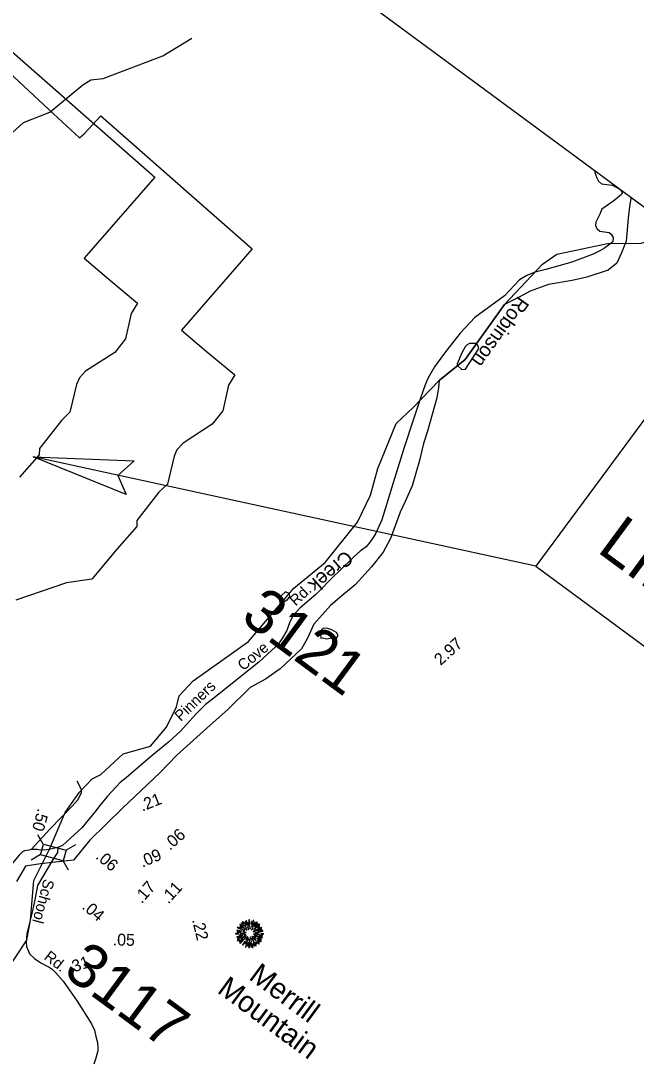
# Model space of a CAD drawing. Extents: x 945666 to 965748, y 644452 to 663300.
# Drawn here: x 954740 to 955579, y 658587 to 660009 of the extents above; entities that cross this region are included whole.
import ezdxf

# ---------------------------------------------------------------- set-up
doc = ezdxf.new("R2010")
doc.units = 0
for name, color, linetype in [('Exist Boundary Political City Limit New', 7, 'Continuous'), ('Exist Boundary Political Urban Extension UEB', 7, 'Continuous'), ('Exist Geographical Mountain Summit CELL', 7, 'Continuous'), ('Exist Geographical Mountain Summit Label', 7, 'Continuous'), ('Exist Hydrographic Creek Single Shore', 7, 'Continuous'), ('Exist Hydrographic Pond Under 1500 Sq Ft', 7, 'Continuous'), ('Exist Road Secondary Mileage Tenths English Label', 7, 'Continuous'), ('Exist Road Secondary Structure Standard Bridge CELL', 7, 'Continuous'), ('Exist Road Secondary Type 51 Attributed', 7, 'Continuous'), ('Exist Road Secondary Type 51 Label', 7, 'Continuous'), ('Old_Level_1', 7, 'Continuous'), ('Old_Level_28', 7, 'Continuous'), ('Old_Level_48', 7, 'Continuous'), ('Prop EOT', 7, 'Continuous'), ('Prop Paved Shoulder', 7, 'Continuous'), ('Prop Terminator CELL', 7, 'Continuous')]:
    doc.layers.add(name, color=color, linetype=linetype)

msp = doc.modelspace()

# ---------------------------------------------------------------- linework, layer by layer
at = {"layer": 'Exist Boundary Political City Limit New'}
msp.add_lwpolyline([(954716, 659977.3), (954922.3, 659795.6), (954826, 659685), (954859.6, 659656.3), (954898.7, 659623.7), (954890, 659609.6), (954882.3, 659575), (954867.7, 659556.4), (954828.1, 659530.8), (954819.8, 659521.7), (954815.8, 659512.9), (954806.6, 659474.9), (954795.1, 659463.6), (954765.2, 659425.2), (954764.8, 659416.9), (954738.1, 659386.3)], dxfattribs=at)
at = {"layer": 'Exist Boundary Political Urban Extension UEB'}
msp.add_lwpolyline([(955572.1, 659768.2), (955570.4, 659758.8), (955568.2, 659739.6), (955565.2, 659708.1), (955558.8, 659692.3), (955552.7, 659678.3), (955540.7, 659668.8), (955511.9, 659659.3), (955491.9, 659654.7), (955459.3, 659649.2), (955434.3, 659640.2), (955418.4, 659631.4), (955413, 659628.8), (955399.4, 659621.7), (955345.6, 659546.9), (955310.4, 659518.1), (955309.2, 659508.6), (955307.2, 659494.5), (955294.5, 659448.8), (955289, 659432.3), (955283.7, 659409.1), (955273.6, 659374.3), (955263.7, 659352.8), (955257.3, 659338.5), (955243.8, 659302.4), (955234.1, 659283.7), (955217.9, 659263.7), (955195.8, 659239.4), (955177.6, 659224.5), (955161.9, 659211), (955139.4, 659185.5), (955130.6, 659166.7), (955122.3, 659151.8), (955093.4, 659124.5), (955073.6, 659110.8), (955052.5, 659099.1), (955022.4, 659069.7), (954993.3, 659043.5), (954952.4, 659006.7), (954929.2, 658982.9), (954878.3, 658934.6), (954834, 658891), (954811.5, 658863.6), (954766.3, 658858.6), (954745.9, 658855.4), (954733.6, 658834.7)], dxfattribs=at)
at = {"layer": 'Exist Geographical Mountain Summit CELL'}
for points in [[(955035.3, 658772), (955035.1, 658771.3), (955039.7, 658769.6), (955039.7, 658770.1)], [(955038.3, 658773), (955041.5, 658770.9), (955041.8, 658771.3), (955038.6, 658773.7)], [(955038.4, 658775.8), (955045.4, 658769.5), (955045.7, 658769.8), (955038.8, 658776.3)], [(955040.3, 658777.8), (955043.9, 658773.6), (955044.3, 658773.9), (955040.8, 658778.2)], [(955042.1, 658779.6), (955043.8, 658776.9), (955044.1, 658777.2), (955042.6, 658780)], [(955044.8, 658774.8), (955047.1, 658771.2), (955047.4, 658771.4), (955045.3, 658775.1)], [(955045.2, 658779), (955046.6, 658775.3), (955047.1, 658775.4), (955045.8, 658779.2)], [(955046.8, 658780.9), (955048.6, 658774.7), (955049, 658774.8), (955047.5, 658781.1)], [(955049, 658772.6), (955050.2, 658768.7), (955050.6, 658768.8), (955049.5, 658772.7)], [(955049.5, 658778.4), (955050.7, 658772.9), (955051.1, 658772.9), (955050.2, 658778.8)], [(955050.8, 658782), (955051.7, 658775.3), (955052.2, 658775.3), (955051.6, 658782.1)], [(955052.1, 658772.5), (955052.3, 658769.7), (955052.7, 658769.7), (955052.7, 658772.5)], [(955053.8, 658780), (955053.8, 658776.5), (955054.1, 658776.5), (955054.5, 658780.1)], [(955056.6, 658781.4), (955054.2, 658772.4), (955054.6, 658772.3), (955057.4, 658781.3)], [(955056.2, 658773.4), (955056.5, 658773.3), (955059.2, 658779), (955058.7, 658779.2)], [(955056.6, 658766.1), (955056.8, 658765.7), (955068.4, 658770.8), (955068.1, 658771.6)], [(955058, 658768.6), (955065.5, 658775.6), (955065, 658776.2), (955057.7, 658769)], [(955061.4, 658779.4), (955057.8, 658773.7), (955058.2, 658773.5), (955062.1, 658779.1)], [(955058.9, 658772.5), (955059.3, 658772.2), (955063.3, 658776.9), (955062.8, 658777.3)], [(955062.5, 658771), (955062.8, 658770.6), (955065.9, 658772.7), (955065.5, 658773.2)], [(955032.6, 658763.6), (955032.6, 658763), (955037.2, 658763), (955037.2, 658763.5)], [(955034.2, 658768.3), (955034.2, 658767.6), (955040.4, 658766.2), (955040.6, 658766.8)], [(955034.3, 658759.2), (955034.4, 658758.7), (955042.3, 658760.5), (955042.2, 658761)], [(955034.8, 658765.3), (955039.2, 658764.8), (955039.2, 658765.3), (955035, 658766)], [(955040.9, 658759.4), (955035.3, 658757.2), (955035.4, 658756.7), (955041.1, 658758.8)], [(955038.3, 658761.3), (955041.7, 658761.7), (955041.6, 658762.2), (955038.1, 658761.9)], [(955038.3, 658750.5), (955038.7, 658750), (955046.9, 658758.3), (955046.7, 658758.7)], [(955039.4, 658763.5), (955039.4, 658762.9), (955045.2, 658763.2), (955045.2, 658763.6)], [(955039.6, 658756.9), (955039.9, 658756.3), (955047.2, 658760.4), (955047, 658760.7)], [(955041, 658769.6), (955040.8, 658769), (955044.9, 658767.3), (955045.1, 658767.8)], [(955042.8, 658766), (955042.7, 658765.3), (955046.8, 658764.7), (955047, 658765.1)], [(955044.1, 658761.5), (955044.2, 658760.9), (955046.6, 658761.9), (955046.5, 658762.2)], [(955049, 658759.4), (955046.6, 658755.2), (955047, 658754.9), (955049.4, 658759.2)], [(955046.8, 658769.5), (955048.4, 658767.9), (955048.6, 658768.1), (955047.2, 658769.9)], [(955052.4, 658758.7), (955053.7, 658752), (955054.3, 658752.3), (955052.8, 658758.8)], [(955056.3, 658771.3), (955054.2, 658768.2), (955054.5, 658768), (955056.8, 658771.1)], [(955054.9, 658759.6), (955060.4, 658753.7), (955060.8, 658754.1), (955055.3, 658759.9)], [(955057.1, 658762.8), (955057, 658762.4), (955064.9, 658762.4), (955064.9, 658763.1)], [(955057.5, 658759.9), (955057.3, 658759.6), (955060.4, 658757.3), (955060.9, 658757.8)], [(955058.6, 658761.2), (955058.6, 658760.9), (955068.9, 658757.8), (955069.1, 658758.5)], [(955058.9, 658764.6), (955059, 658764.2), (955069.8, 658766.7), (955069.7, 658767.5)], [(955063.4, 658757.7), (955067.7, 658755.5), (955068, 658756.2), (955063.4, 658758)], [(955068.4, 658769.2), (955063.6, 658767.4), (955063.8, 658767), (955068.6, 658768.6)], [(955065.4, 658760.7), (955069.4, 658760.2), (955069.5, 658760.9), (955065.4, 658761.1)], [(955067.1, 658763.1), (955067.1, 658762.7), (955070.8, 658762.6), (955070.7, 658763.3)], [(955034.8, 658754.4), (955035.1, 658753.7), (955038.1, 658755.5), (955038, 658755.9)], [(955038.1, 658752.3), (955042.6, 658755.8), (955042.3, 658756.2), (955037.7, 658752.7)], [(955045.1, 658752.8), (955042.2, 658748), (955042.7, 658747.8), (955045.6, 658752.4)], [(955045.9, 658749.5), (955047.6, 658753), (955047.3, 658753.3), (955045.4, 658749.7)], [(955048, 658751.4), (955046, 658744.8), (955046.6, 658744.7), (955048.4, 658751.2)], [(955050, 658757.2), (955048.6, 658753.4), (955049.2, 658753.3), (955050.3, 658757.2)], [(955049.6, 658751.2), (955049, 658746.9), (955049.6, 658746.8), (955050.1, 658751)], [(955051.3, 658755.9), (955050.9, 658744.1), (955051.5, 658744.2), (955051.7, 658755.8)], [(955052.7, 658750.7), (955053.6, 658745.3), (955054.2, 658745.3), (955053.2, 658750.8)], [(955054.5, 658749.5), (955055.7, 658744.4), (955056.4, 658744.5), (955054.9, 658749.6)], [(955054.9, 658756.5), (955060.1, 658746.5), (955060.7, 658746.9), (955055.2, 658756.7)], [(955056.3, 658749.9), (955057.9, 658746.6), (955058.5, 658746.8), (955056.9, 658750.1)], [(955059.7, 658751.3), (955061.3, 658748.9), (955061.8, 658749.2), (955060.1, 658751.5)], [(955061.7, 658752), (955064.1, 658749), (955064.6, 658749.6), (955062.1, 658752.4)], [(955062, 658756.5), (955067.7, 658752.8), (955068.1, 658753.3), (955062.2, 658756.8)], [(955062.6, 658754.1), (955065.2, 658751.8), (955065.5, 658752.3), (955062.9, 658754.4)]]:
    msp.add_lwpolyline(points, close=True, dxfattribs=at)
at = {"layer": 'Exist Hydrographic Creek Single Shore'}
for points in [[(954208.1, 659852.7), (954218.8, 659848.8), (954227.8, 659830.5), (954283.4, 659794.3), (954309.8, 659785.8), (954409.1, 659775), (954444, 659784.2), (954478.8, 659805.3), (954539.6, 659812.3), (954592.2, 659810.6), (954684.5, 659831), (954728, 659856.2), (954743.3, 659870.2), (954779.4, 659884.4), (954824.4, 659921.8), (954835.3, 659928.5), (954851.9, 659930.3), (954933.2, 659961.3), (954972.8, 659985.1)], [(955399.4, 659621.7), (955451.4, 659676.9), (955470.6, 659690.6), (955540, 659705), (955586, 659705.6), (955636.3, 659720.9)], [(955310.4, 659518.1), (955345.6, 659546.9), (955399.4, 659621.7)], [(954819.8, 658956.5), (954836.9, 658974.6), (954848.6, 658980.6), (954879.2, 659008.7), (954916.5, 659019.2), (954938.3, 659045), (954951.9, 659072.7), (954955.5, 659087.7), (954974.7, 659108.4), (955050.4, 659162), (955112, 659234.6), (955155, 659269.8), (955198.7, 659324.9), (955216.8, 659361.6), (955226.5, 659398.2), (955251.6, 659459.5), (955274.8, 659481.5), (955310.4, 659518.1)], [(954421.5, 658112.4), (954444.5, 658163.9), (954453.2, 658188.9), (954457.4, 658230.8), (954466.6, 658251.2), (954526.1, 658336.7), (954530.9, 658356.6), (954524.2, 658393.5), (954532, 658420.8), (954541.6, 658436.5), (954567.8, 658457.3), (954573.5, 658466.3), (954575.4, 658496.6), (954594.7, 658522.6), (954601.5, 658526), (954630.4, 658560.7), (954654.5, 658613.7), (954748.1, 658754.6), (954752.9, 658781.6), (954757.2, 658835.8), (954778.6, 658878.5), (954800.3, 658928.5), (954819.8, 658956.5)]]:
    msp.add_lwpolyline(points, dxfattribs=at)
at = {"layer": 'Exist Hydrographic Pond Under 1500 Sq Ft'}
for points in [[(955362.2, 659566.9), (955359.4, 659568.4), (955351.8, 659568.4), (955348.7, 659567), (955345.7, 659564), (955341.4, 659556.1), (955334.9, 659540.8), (955335.5, 659538.6), (955341.3, 659533)], [(955341.3, 659533), (955346.1, 659533.6), (955362.3, 659558.2), (955364.2, 659561.9), (955363, 659566.2), (955362.2, 659566.9)], [(955106.7, 659223.9), (955105.6, 659227.5), (955100.5, 659229.9), (955094.9, 659224.1), (955094.3, 659217.9), (955096.3, 659216.3), (955097.5, 659216)], [(955106.7, 659223.9), (955102.6, 659218.3), (955098.8, 659216), (955097.5, 659216)], [(955172.7, 659170), (955170.2, 659174.3), (955163.8, 659178), (955158.5, 659179.6), (955152.1, 659180), (955150, 659177.7), (955148.6, 659175.2), (955148.3, 659171.8), (955148.9, 659166.7)], [(955148.9, 659166.7), (955151.1, 659166.9), (955156.7, 659165.7), (955164.4, 659167), (955170.1, 659166.7), (955172.7, 659170)]]:
    msp.add_lwpolyline(points, dxfattribs=at)
at = {"layer": 'Exist Road Secondary Structure Standard Bridge CELL'}
for p, q in [((954770.3, 658885.3), (954763, 658898)), ((954766.5, 658871.1), (954753.7, 658863.8)), ((954814.2, 658884.4), (954801.5, 658877.1)), ((954804.8, 658849.8), (954797.5, 658862.6))]:
    msp.add_line(p, q, dxfattribs=at)
msp.add_lwpolyline([(954797.5, 658862.6), (954766.5, 658871), (954770.4, 658885.5), (954801.5, 658877.1)], close=True, dxfattribs=at)
at = {"layer": 'Exist Road Secondary Type 51 Attributed'}
for points in [[(955522.2, 659805), (955522.7, 659802), (955525.4, 659794.8), (955527.8, 659790.1), (955531.8, 659786.4), (955546.5, 659784.6), (955553.7, 659781.2), (955558, 659778.4), (955560.1, 659774.3), (955559, 659771.8), (955548.7, 659763.1), (955532.3, 659751.9), (955529.6, 659744.9), (955524, 659734.2), (955523.5, 659729.3), (955525.7, 659725.1), (955529.4, 659722.1), (955542.3, 659720.2), (955545, 659718), (955547.5, 659713.4), (955547, 659707.2), (955543.3, 659704), (955535.7, 659698.8), (955529.3, 659695.3), (955520.5, 659690.6), (955491.1, 659679.4), (955455.6, 659669.8), (955441.3, 659665.9), (955435.4, 659663.9), (955429.8, 659661.4), (955420, 659655.3), (955399.6, 659633.6), (955359, 659603.9), (955339.1, 659582.6), (955323.9, 659563.7), (955317.7, 659555.5), (955303.8, 659536.9), (955294.7, 659520.8), (955291.4, 659512.4), (955285.1, 659495.3)], [(955285.1, 659495.3), (955275.5, 659465.5), (955262.2, 659425.3), (955247.7, 659378.3), (955232, 659328.2), (955223.8, 659309.7), (955220.4, 659303.8), (955216.3, 659298.1), (955210.8, 659291.1), (955202.7, 659285.4), (955194.8, 659278.5), (955172.8, 659257.1), (955167.8, 659252.6), (955141.9, 659226.2), (955120.2, 659207.4), (955111.2, 659197.5), (955106.5, 659188.7), (955102.4, 659177), (955096.8, 659166.9), (955090.3, 659157.6), (955082.5, 659150.7), (955064.2, 659133.7), (955001.1, 659083.5), (954991.8, 659076), (954978.8, 659063.4), (954965.5, 659048.8), (954958.1, 659040.2), (954941, 659024.4), (954918.7, 659006.3), (954893.6, 658985.1), (954883.3, 658976.1), (954875.3, 658969.5), (954857.8, 658951), (954847.4, 658938.1)], [(954753.6, 658878), (954779.9, 658906.5), (954809.8, 658937.3), (954817.3, 658946.1), (954822.6, 658955.3), (954822.3, 658959.8), (954816.5, 658971.3)], [(954847.4, 658938.1), (954841.4, 658930.6), (954822.9, 658907.9), (954796.7, 658883.7), (954790.3, 658881.1)], [(954744.8, 658876.3), (954742.1, 658875), (954737.2, 658870.2), (954720.4, 658850.5), (954715.4, 658847), (954708.5, 658842.6), (954701, 658837.8), (954682.7, 658832.4), (954668.7, 658823.3), (954659, 658815.7), (954654.7, 658814.4), (954650.8, 658814.5), (954644.9, 658816.3), (954639.5, 658818.9), (954634.2, 658823.3), (954630.2, 658827.9), (954614, 658851), (954600.5, 658865.7), (954593.6, 658873.6), (954588.8, 658877.3)], [(954753.6, 658878), (954750.6, 658877.2), (954744.8, 658876.3)], [(954790.3, 658881.1), (954789.5, 658874.2), (954782.9, 658863.7), (954762.3, 658828.8), (954758.9, 658809.6), (954755.6, 658794.6), (954748, 658763.6), (954747.1, 658751.3), (954747.2, 658745.9), (954750.5, 658738.2), (954751.7, 658735.8), (954758.4, 658729.3), (954762.7, 658726.2), (954767.1, 658723.6), (954778.4, 658717.6), (954782.5, 658714.9), (954787.2, 658710.5), (954797.6, 658698.7), (954816.7, 658671.2), (954836.3, 658640.2), (954840, 658631.8), (954842.2, 658623), (954844.4, 658614.6), (954844.9, 658608), (954844.9, 658603.3), (954842.2, 658593.4), (954839.4, 658585.1)], [(954778.3, 658878), (954771.9, 658877.4), (954763.9, 658877.8), (954762, 658878), (954753.6, 658878)], [(954790.3, 658881.1), (954778.3, 658878)]]:
    msp.add_lwpolyline(points, dxfattribs=at)
at = {"layer": 'Old_Level_1'}
msp.add_lwpolyline([(953667.4, 661172.9), (956829.7, 658840.6), (955088.6, 656479.8), (951926.2, 658812.1)], close=True, dxfattribs=at)
at = {"layer": 'Old_Level_28'}
for points in [[(954708.2, 660405.3), (954708.6, 660402.3), (954716.8, 660382.9), (954727.8, 660367.4), (954737.9, 660351.5), (954751.5, 660322.1), (954763.5, 660296.6), (954766.2, 660266.3), (954763.9, 660235.2), (954749.5, 660200.8), (954687.3, 660119.4), (954627.2, 660027.9), (954784.3, 659882)], [(954784.3, 659882), (954819.7, 659849.2), (954825.9, 659854.8), (954848.9, 659879.2), (955055.2, 659697.6), (954958.9, 659587), (954992.5, 659558.3), (955031.6, 659525.7), (955022.9, 659511.6), (955015.2, 659476.9), (955000.6, 659458.4), (954961, 659432.7), (954952.7, 659423.7), (954948.7, 659414.8), (954939.6, 659376.9), (954928, 659365.6), (954898.1, 659327.2), (954897.7, 659318.9), (954871, 659288.3), (954836.4, 659247.2), (954802.2, 659242.2), (954732.8, 659218.2)]]:
    msp.add_lwpolyline(points, dxfattribs=at)
at = {"layer": 'Prop EOT'}
msp.add_line((955442.2, 659264.8), (954756.3, 659413.9), dxfattribs=at)
msp.add_lwpolyline([(956249.9, 659022.7), (955611.1, 659493.8), (955442.2, 659264.8), (956081, 658793.7)], close=True, dxfattribs=at)
at = {"layer": 'Prop Terminator CELL'}
msp.add_lwpolyline([(954883.3, 659362.5), (954756.3, 659413.9), (954894.1, 659408.5), (954872.1, 659388.7)], close=True, dxfattribs=at)

# ---------------------------------------------------------------- texts
at = {"layer": 'Exist Geographical Mountain Summit Label'}
for s, p in [('Merrill', (955049.4, 658702)), ('Mountain', (955006.2, 658683.9))]:
    msp.add_text(s, height=28.58, rotation=323.5908, dxfattribs=at).set_placement(p)
at = {"layer": 'Exist Road Secondary Mileage Tenths English Label'}
for s, rotation, p in [('2.97', 41.9078, (955312.3, 659128.5)), ('.21', 21.6906, (954905.4, 658929.8)), ('.50', 254.2702, (954763, 658934.9)), ('.06', 41.3365, (954943, 658876.2)), ('.06', 319.5433, (954840.7, 658866.8)), ('.09', 23.1624, (954905.5, 658853.2)), ('.17', 48.9871, (954904.7, 658803.4)), ('.11', 47.4311, (954940.9, 658803.1)), ('.04', 319.7404, (954822, 658798.3)), ('.22', 283.7625, (954973.1, 658782)), ('.05', 358.7288, (954864.9, 658747.3)), ('.31', 18.7677, (954806.7, 658708.5))]:
    msp.add_text(s, height=16.24, rotation=rotation, dxfattribs=at).set_placement(p)
at = {"layer": 'Exist Road Secondary Type 51 Label'}
for s, rotation, p in [('Rd.', 43.1107, (955114.7, 659209.5)), ('Cove', 39.9153, (955043.1, 659121.3)), ('Pinners', 44.18, (954958, 659052.1)), ('School', 254.9105, (954771.2, 658838.9)), ('Rd.', 322.1878, (954770.2, 658729.4))]:
    msp.add_text(s, height=15, rotation=rotation, dxfattribs=at).set_placement(p)
at = {"layer": 'Old_Level_1'}
for s, p in [('3121', (955037.7, 659191.6)), ('3117', (954795.7, 658708.2))]:
    msp.add_text(s, height=60, rotation=323.5908, dxfattribs=at).set_placement(p)
at = {"layer": 'Old_Level_48'}
msp.add_text('LIMITS', height=64.23, rotation=323.5908, dxfattribs=at).set_placement((955523.8, 659285.5))
at = {"layer": 'Prop Paved Shoulder'}
for s, rotation, p in [('Robinson', 234.3033, (955418.4, 659634.5)), ('Creek', 221.0076, (955182.4, 659287.4))]:
    msp.add_text(s, height=19.49, rotation=rotation, dxfattribs=at).set_placement(p)

doc.saveas('drawing.dxf')
